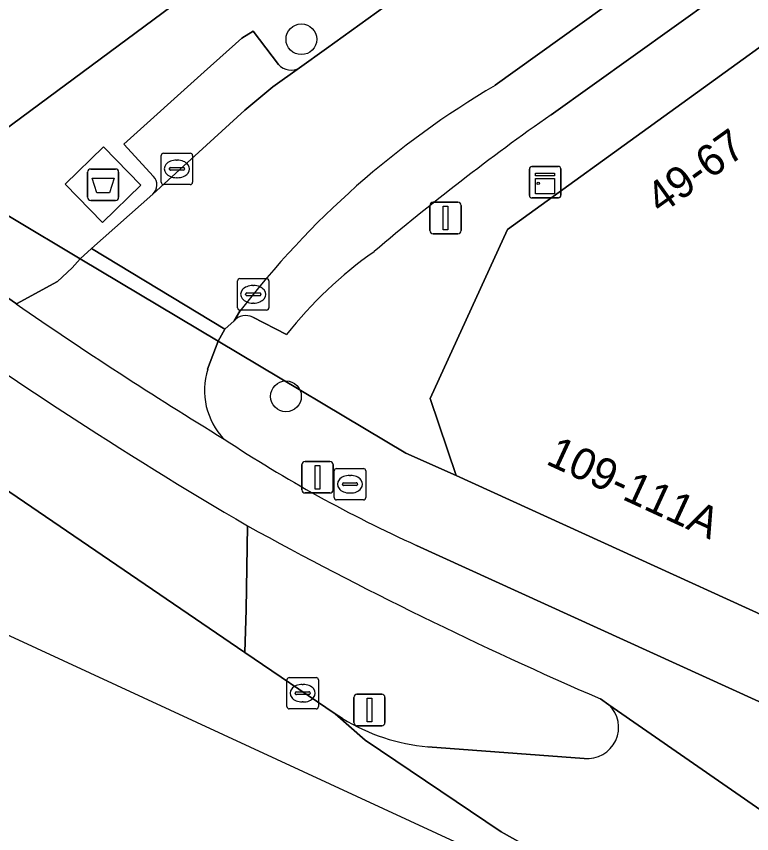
# Model space of a CAD drawing. Extents: x 161881 to 162523, y 381678 to 382381.
# Drawn here: x 162165.21 to 162188.61, y 381835.76 to 381861.78 of the extents above; entities that cross this region are included whole.
import ezdxf

# ---------------------------------------------------------------- set-up
doc = ezdxf.new("R2010")
doc.units = 0
for name, color, linetype in [('IMGEO_Afval_apart_plaats', 7, 'Continuous'), ('IMGEO_Berm_groen', 7, 'Continuous'), ('IMGEO_Boom', 7, 'Continuous'), ('IMGEO_Brandkraan', 7, 'Continuous'), ('IMGEO_Fietspad_open', 7, 'Continuous'), ('IMGEO_Kast', 7, 'Continuous'), ('IMGEO_Kolk', 7, 'Continuous'), ('IMGEO_Lichtmast', 7, 'Continuous'), ('IMGEO_Pand', 7, 'Continuous'), ('IMGEO_Pand_nummerreeks', 7, 'Continuous'), ('IMGEO_Parkeervlak_open', 7, 'Continuous'), ('IMGEO_Rijbaan_lokaal_gesloten', 7, 'Continuous'), ('IMGEO_Rijbaan_lokaal_open', 7, 'Continuous'), ('IMGEO_Voetpad_gesloten', 7, 'Continuous'), ('IMGEO_Voetpad_open', 7, 'Continuous')]:
    doc.layers.add(name, color=color, linetype=linetype)

msp = doc.modelspace()

# ---------------------------------------------------------------- linework, layer by layer
at = {"layer": 'IMGEO_Afval_apart_plaats'}
for p, q in [((162167.573, 381856.917), (162168.363, 381856.917)), ((162168.363, 381856.917), (162167.573, 381856.917)), ((162167.473, 381856.017), (162167.473, 381856.817)), ((162167.473, 381856.817), (162167.473, 381856.017)), ((162168.463, 381856.817), (162168.463, 381856.017)), ((162168.463, 381856.017), (162168.463, 381856.817)), ((162168.363, 381855.917), (162167.573, 381855.917)), ((162167.573, 381855.917), (162168.363, 381855.917))]:
    msp.add_line(p, q, dxfattribs=at)
msp.add_lwpolyline([(162167.616, 381856.631), (162168.32, 381856.631), (162168.171, 381856.161), (162167.765, 381856.161), (162167.616, 381856.631)], dxfattribs=at)
for centre, start, end in [((162167.573, 381856.817), 90, 180), ((162167.573, 381856.817), 90, 180), ((162168.363, 381856.817), 0, 90), ((162168.363, 381856.817), 360, 90), ((162167.573, 381856.017), 180, 270), ((162167.573, 381856.017), 180, 270), ((162168.363, 381856.017), 270, 0), ((162168.363, 381856.017), 270, 0)]:
    msp.add_arc(centre, 0.1, start, end, dxfattribs=at)
at = {"layer": 'IMGEO_Berm_groen'}
for points in [[(162172.562, 381845.561), (162172.524, 381842.897), (162172.48, 381841.526), (162175.355, 381839.579), (162175.591, 381839.426)], [(162184.069, 381839.866), (162183.799, 381840.053)], [(162178.306, 381838.523), (162183.281, 381838.158)]]:
    msp.add_lwpolyline(points, dxfattribs=at)
for centre, radius, start, end in [((162236.795, 381962.387), 133.32, 241.19739, 246.57753), ((162183.382, 381839.147), 0.994, 264.1725, 46.2942), ((162178.879, 381844.779), 6.282, 238.4392, 264.7669)]:
    msp.add_arc(centre, radius, start, end, dxfattribs=at)
at = {"layer": 'IMGEO_Boom'}
for centre in [(162174.279, 381861.047), (162173.788, 381849.681)]:
    msp.add_circle(centre, 0.489, dxfattribs=at)
at = {"layer": 'IMGEO_Brandkraan'}
for p, q in [((162175.326, 381846.459), (162175.326, 381847.311)), ((162175.401, 381847.385), (162176.253, 381847.385)), ((162176.327, 381847.311), (162176.327, 381846.459)), ((162175.814, 381847.165), (162175.839, 381847.165)), ((162175.585, 381846.879), (162175.585, 381846.891)), ((162176.023, 381846.842), (162175.625, 381846.842)), ((162175.628, 381846.928), (162176.026, 381846.928)), ((162176.069, 381846.891), (162176.069, 381846.879)), ((162175.837, 381846.605), (162175.812, 381846.605)), ((162176.253, 381846.385), (162175.401, 381846.385))]:
    msp.add_line(p, q, dxfattribs=at)
for points in [[(162175.326, 381846.459), (162175.326, 381847.311)], [(162175.401, 381847.385), (162176.253, 381847.385)], [(162176.327, 381847.311), (162176.327, 381846.459)], [(162176.253, 381846.385), (162175.401, 381846.385)]]:
    msp.add_lwpolyline(points, dxfattribs=at)
for centre, radius, start, end in [((162175.403, 381847.309), 0.0765, 91.552, 178.448), ((162175.403, 381847.309), 0.0765, 91.552, 178.448), ((162176.251, 381847.309), 0.0765, 1.552, 88.448), ((162176.251, 381847.309), 0.0765, 1.552, 88.448), ((162175.625, 381846.888), 0.0403, 85.8775, 175.7526), ((162175.622, 381846.878), 0.0366, 178.938, 274.7102), ((162176.026, 381846.885), 0.043, 264.8664, 352.4533), ((162176.03, 381846.89), 0.0386, 1.7309, 96.639), ((162175.403, 381846.461), 0.0765, 181.552, 268.448), ((162175.403, 381846.461), 0.0765, 181.552, 268.448), ((162176.251, 381846.461), 0.0765, 271.552, 358.448), ((162176.251, 381846.461), 0.0765, 271.552, 358.448)]:
    msp.add_arc(centre, radius, start, end, dxfattribs=at)
for centre, major_axis, ratio, start_param, end_param in [((162175.813, 381846.885), (-0.387, 0.002), 0.722429, 4.712389, 7.853982), ((162175.838, 381846.885), (-0.39, 0.002), 0.717154, 1.570796, 4.712389)]:
    msp.add_ellipse(centre, major_axis=major_axis, ratio=ratio, start_param=start_param, end_param=end_param, dxfattribs=at)
at = {"layer": 'IMGEO_Fietspad_open'}
for points in [[(162165.207, 381852.621), (162159.359, 381856.676), (162153.733, 381860.844), (162148.22, 381865.171), (162143.628, 381869.029), (162139.164, 381873.055), (162135.64, 381876.643), (162133.655, 381878.876), (162129.811, 381883.512), (162122.303, 381893.442)], [(162297.281, 381790.934), (162283.991, 381796.906), (162276.913, 381800.086), (162237.824, 381817.651), (162177.947, 381844.935)], [(162183.799, 381840.053), (162184.069, 381839.866), (162192.812, 381833.805), (162194.089, 381833.367), (162198.754, 381831.251), (162197.694, 381828.855), (162197.222, 381827.799), (162199.963, 381826.58), (162201.558, 381830.008), (162248.9, 381808.653), (162250.093, 381808.023), (162257.97, 381806.387), (162264.876, 381803.292), (162275.916, 381798.35), (162283.117, 381795.079), (162296.058, 381789.157)]]:
    msp.add_lwpolyline(points, dxfattribs=at)
for centre, radius, start, end in [((162242.708, 381965.423), 138.879, 233.95977, 239.66292), ((162245.71, 381969.21), 141.682, 235.37531, 238.56599), ((162196.27, 381885.32), 44.347, 236.5431, 245.5958), ((162236.795, 381962.387), 133.32, 241.19739, 246.57753)]:
    msp.add_arc(centre, radius, start, end, dxfattribs=at)
at = {"layer": 'IMGEO_Kast'}
for p, q in [((162181.537, 381856.073), (162181.537, 381856.914)), ((162181.537, 381856.914), (162181.537, 381856.073)), ((162181.612, 381856.998), (162182.453, 381856.998)), ((162182.453, 381856.998), (162181.612, 381856.998)), ((162182.537, 381856.923), (162182.537, 381856.082)), ((162182.537, 381856.082), (162182.537, 381856.923)), ((162182.462, 381855.998), (162181.621, 381855.998)), ((162181.621, 381855.998), (162182.462, 381855.998))]:
    msp.add_line(p, q, dxfattribs=at)
for points in [[(162181.732, 381856.788), (162182.332, 381856.788), (162182.332, 381856.703), (162181.732, 381856.703), (162181.732, 381856.788)], [(162181.732, 381856.613), (162182.332, 381856.613), (162182.332, 381856.124), (162181.732, 381856.124), (162181.732, 381856.613)]]:
    msp.add_lwpolyline(points, dxfattribs=at)
msp.add_circle((162181.816, 381856.462), 0.0377, dxfattribs=at)
for centre, start, end in [((162181.615, 381856.92), 92.4484, 184.2845), ((162181.615, 381856.92), 92.4484, 184.2845), ((162182.459, 381856.92), 2.4484, 94.2845), ((162182.459, 381856.92), 2.4484, 94.2845), ((162182.459, 381856.076), 272.4484, 4.2845), ((162182.459, 381856.076), 272.4484, 4.2845), ((162181.615, 381856.076), 182.4484, 274.2845), ((162181.615, 381856.076), 182.4484, 274.2845)]:
    msp.add_arc(centre, 0.0779, start, end, dxfattribs=at)
at = {"layer": 'IMGEO_Kolk'}
for p, q in [((162169.892, 381857.42), (162170.744, 381857.42)), ((162169.817, 381856.494), (162169.817, 381857.346)), ((162170.305, 381857.2), (162170.33, 381857.2)), ((162170.818, 381857.346), (162170.818, 381856.494)), ((162170.076, 381856.914), (162170.076, 381856.926)), ((162170.514, 381856.877), (162170.116, 381856.877)), ((162170.119, 381856.963), (162170.517, 381856.963)), ((162170.56, 381856.926), (162170.56, 381856.914)), ((162170.328, 381856.64), (162170.303, 381856.64)), ((162170.744, 381856.42), (162169.892, 381856.42)), ((162172.246, 381852.503), (162172.246, 381853.355)), ((162172.321, 381853.429), (162173.173, 381853.429)), ((162173.247, 381853.355), (162173.247, 381852.503)), ((162172.548, 381852.972), (162172.946, 381852.972)), ((162172.734, 381853.209), (162172.759, 381853.209)), ((162172.505, 381852.923), (162172.505, 381852.935)), ((162172.943, 381852.886), (162172.545, 381852.886)), ((162172.989, 381852.935), (162172.989, 381852.923)), ((162172.757, 381852.649), (162172.732, 381852.649)), ((162173.173, 381852.429), (162172.321, 381852.429)), ((162173.895, 381840.733), (162174.747, 381840.733)), ((162173.82, 381839.807), (162173.82, 381840.659)), ((162174.308, 381840.513), (162174.333, 381840.513)), ((162174.821, 381840.659), (162174.821, 381839.807)), ((162174.079, 381840.227), (162174.079, 381840.239)), ((162174.122, 381840.276), (162174.52, 381840.276)), ((162174.563, 381840.239), (162174.563, 381840.227)), ((162174.517, 381840.19), (162174.119, 381840.19)), ((162174.331, 381839.953), (162174.306, 381839.953)), ((162174.747, 381839.733), (162173.895, 381839.733))]:
    msp.add_line(p, q, dxfattribs=at)
for points in [[(162169.892, 381857.42), (162170.744, 381857.42)], [(162169.817, 381856.494), (162169.817, 381857.346)], [(162170.818, 381857.346), (162170.818, 381856.494)], [(162170.744, 381856.42), (162169.892, 381856.42)], [(162172.246, 381852.503), (162172.246, 381853.355)], [(162172.321, 381853.429), (162173.173, 381853.429)], [(162173.247, 381853.355), (162173.247, 381852.503)], [(162173.173, 381852.429), (162172.321, 381852.429)], [(162173.895, 381840.733), (162174.747, 381840.733)], [(162173.82, 381839.807), (162173.82, 381840.659)], [(162174.821, 381840.659), (162174.821, 381839.807)], [(162174.747, 381839.733), (162173.895, 381839.733)]]:
    msp.add_lwpolyline(points, dxfattribs=at)
for centre, radius, start, end in [((162169.894, 381857.344), 0.0765, 91.552, 178.448), ((162169.894, 381857.344), 0.0765, 91.552, 178.448), ((162170.742, 381857.344), 0.0765, 1.552, 88.448), ((162170.742, 381857.344), 0.0765, 1.552, 88.448), ((162170.116, 381856.923), 0.0403, 85.8775, 175.7526), ((162170.113, 381856.913), 0.0366, 178.938, 274.7102), ((162170.517, 381856.92), 0.043, 264.8664, 352.4533), ((162170.521, 381856.925), 0.0386, 1.7309, 96.639), ((162169.894, 381856.496), 0.0765, 181.552, 268.448), ((162169.894, 381856.496), 0.0765, 181.552, 268.448), ((162170.742, 381856.496), 0.0765, 271.552, 358.448), ((162170.742, 381856.496), 0.0765, 271.552, 358.448), ((162172.323, 381853.353), 0.0765, 91.552, 178.448), ((162172.323, 381853.353), 0.0765, 91.552, 178.448), ((162173.171, 381853.353), 0.0765, 1.552, 88.448), ((162173.171, 381853.353), 0.0765, 1.552, 88.448), ((162172.545, 381852.932), 0.0403, 85.8775, 175.7526), ((162172.95, 381852.934), 0.0386, 1.7309, 96.639), ((162172.542, 381852.922), 0.0366, 178.938, 274.7102), ((162172.946, 381852.929), 0.043, 264.8664, 352.4533), ((162172.323, 381852.505), 0.0765, 181.552, 268.448), ((162172.323, 381852.505), 0.0765, 181.552, 268.448), ((162173.171, 381852.505), 0.0765, 271.552, 358.448), ((162173.171, 381852.505), 0.0765, 271.552, 358.448), ((162173.897, 381840.657), 0.0765, 91.552, 178.448), ((162173.897, 381840.657), 0.0765, 91.552, 178.448), ((162174.745, 381840.657), 0.0765, 1.552, 88.448), ((162174.745, 381840.657), 0.0765, 1.552, 88.448), ((162174.119, 381840.236), 0.0403, 85.8775, 175.7526), ((162174.116, 381840.226), 0.0366, 178.938, 274.7102), ((162174.52, 381840.233), 0.043, 264.8664, 352.4533), ((162174.524, 381840.238), 0.0386, 1.7309, 96.639), ((162173.897, 381839.809), 0.0765, 181.552, 268.448), ((162173.897, 381839.809), 0.0765, 181.552, 268.448), ((162174.745, 381839.809), 0.0765, 271.552, 358.448), ((162174.745, 381839.809), 0.0765, 271.552, 358.448)]:
    msp.add_arc(centre, radius, start, end, dxfattribs=at)
for centre, major_axis, ratio, start_param, end_param in [((162170.304, 381856.92), (-0.387, 0.002), 0.722429, 4.712389, 7.853982), ((162170.329, 381856.92), (-0.39, 0.002), 0.717154, 1.570796, 4.712389), ((162172.733, 381852.929), (-0.387, 0.002), 0.722429, 4.712389, 7.853982), ((162172.758, 381852.929), (-0.39, 0.002), 0.717154, 1.570796, 4.712389), ((162174.307, 381840.233), (-0.387, 0.002), 0.722429, 4.712389, 7.853982), ((162174.332, 381840.233), (-0.39, 0.002), 0.717154, 1.570796, 4.712389)]:
    msp.add_ellipse(centre, major_axis=major_axis, ratio=ratio, start_param=start_param, end_param=end_param, dxfattribs=at)
at = {"layer": 'IMGEO_Lichtmast'}
for p, q in [((162178.472, 381855.859), (162179.262, 381855.859)), ((162179.262, 381855.859), (162178.472, 381855.859)), ((162178.372, 381854.959), (162178.372, 381855.759)), ((162178.372, 381855.759), (162178.372, 381854.959)), ((162179.362, 381855.759), (162179.362, 381854.959)), ((162179.362, 381854.959), (162179.362, 381855.759)), ((162179.262, 381854.859), (162178.472, 381854.859)), ((162178.472, 381854.859), (162179.262, 381854.859)), ((162174.297, 381846.707), (162174.297, 381847.507)), ((162174.297, 381847.507), (162174.297, 381846.707)), ((162174.397, 381847.607), (162175.187, 381847.607)), ((162175.187, 381847.607), (162174.397, 381847.607)), ((162175.287, 381847.507), (162175.287, 381846.707)), ((162175.287, 381846.707), (162175.287, 381847.507)), ((162175.187, 381846.607), (162174.397, 381846.607)), ((162174.397, 381846.607), (162175.187, 381846.607)), ((162175.948, 381839.298), (162175.948, 381840.098)), ((162175.948, 381840.098), (162175.948, 381839.298)), ((162176.048, 381840.198), (162176.838, 381840.198)), ((162176.838, 381840.198), (162176.048, 381840.198)), ((162176.938, 381840.098), (162176.938, 381839.298)), ((162176.938, 381839.298), (162176.938, 381840.098)), ((162176.838, 381839.198), (162176.048, 381839.198)), ((162176.048, 381839.198), (162176.838, 381839.198))]:
    msp.add_line(p, q, dxfattribs=at)
for points in [[(162178.792, 381855.734), (162178.942, 381855.734), (162178.942, 381854.984), (162178.792, 381854.984), (162178.792, 381855.734)], [(162174.717, 381847.482), (162174.867, 381847.482), (162174.867, 381846.732), (162174.717, 381846.732), (162174.717, 381847.482)], [(162176.368, 381840.073), (162176.518, 381840.073), (162176.518, 381839.323), (162176.368, 381839.323), (162176.368, 381840.073)]]:
    msp.add_lwpolyline(points, dxfattribs=at)
for centre, start, end in [((162178.472, 381855.759), 90, 180), ((162178.472, 381855.759), 90, 180), ((162179.262, 381855.759), 0, 90), ((162179.262, 381855.759), 360, 90), ((162178.472, 381854.959), 180, 270), ((162178.472, 381854.959), 180, 270), ((162179.262, 381854.959), 270, 0), ((162179.262, 381854.959), 270, 0), ((162174.397, 381847.507), 90, 180), ((162174.397, 381847.507), 90, 180), ((162175.187, 381847.507), 0, 90), ((162175.187, 381847.507), 360, 90), ((162174.397, 381846.707), 180, 270), ((162174.397, 381846.707), 180, 270), ((162175.187, 381846.707), 270, 0), ((162175.187, 381846.707), 270, 0), ((162176.048, 381840.098), 90, 180), ((162176.048, 381840.098), 90, 180), ((162176.838, 381840.098), 0, 90), ((162176.838, 381840.098), 360, 90), ((162176.048, 381839.298), 180, 270), ((162176.048, 381839.298), 180, 270), ((162176.838, 381839.298), 270, 0), ((162176.838, 381839.298), 270, 0)]:
    msp.add_arc(centre, 0.1, start, end, dxfattribs=at)
at = {"layer": 'IMGEO_Pand'}
for points in [[(162167.706, 381866.247), (162166.625, 381867.135), (162166.397, 381869.331), (162167.982, 381870.977), (162172.99, 381864.214), (162173.176, 381864.352), (162176.595, 381866.681), (162173.642, 381870.716), (162171.2, 381874.055), (162168.933, 381877.15), (162167.482, 381875.329), (162166.814, 381874.49), (162162.639, 381869.248), (162160.713, 381866.829), (162156.495, 381861.533), (162162.832, 381856.692), (162170.693, 381862.513), (162168.29, 381864.451), (162167.194, 381865.56)], [(162196.913, 381858.497), (162201.802, 381856.284), (162202.159, 381857.074), (162191.173, 381862.471), (162180.837, 381854.994), (162178.376, 381849.609), (162179.207, 381847.165), (162189.628, 381842.404)]]:
    msp.add_lwpolyline(points, close=True, dxfattribs=at)
at = {"layer": 'IMGEO_Parkeervlak_open'}
for points in [[(162212.528, 381882.597), (162203.872, 381876.38), (162180.448, 381859.581)], [(162182.228, 381858.647), (162187.449, 381862.392), (162186.929, 381863.221)], [(162173.553, 381860.247), (162172.749, 381861.307), (162172.384, 381861.078), (162171.188, 381860.007), (162168.627, 381857.706), (162169.576, 381856.681)], [(162169.555, 381856.117), (162172.481, 381858.791), (162173.371, 381859.537), (162174.221, 381860.14)], [(162172.323, 381852.389), (162172.135, 381852.084)], [(162172.73, 381852.199), (162173.804, 381851.649)]]:
    msp.add_lwpolyline(points, dxfattribs=at)
for centre, radius, start, end in [((162173.949, 381860.583), 0.52, 220.3046, 301.4948), ((162194.807, 381835.174), 28.317, 120.4684, 142.5601), ((162227.388, 381794.436), 78.501, 125.11899, 130.32212), ((162169.286, 381856.409), 0.397, 312.6327, 43.1026), ((162184.541, 381843.096), 13.727, 125.3918, 141.4617), ((162172.505, 381851.766), 0.488, 62.5418, 139.3364)]:
    msp.add_arc(centre, radius, start, end, dxfattribs=at)
at = {"layer": 'IMGEO_Rijbaan_lokaal_gesloten'}
for points in [[(162157.474, 381846.239), (162163.289, 381842.84), (162270.956, 381793.049), (162271.685, 381794.828), (162265.892, 381797.201), (162264.88, 381797.509), (162260.412, 381799.413), (162255.206, 381801.667), (162254.636, 381801.98), (162216.47, 381819.118), (162200.955, 381826.085), (162199.963, 381826.58), (162197.222, 381827.799), (162186.613, 381832.56), (162184.638, 381833.581), (162180.636, 381835.815), (162176.308, 381838.737), (162175.355, 381839.579), (162172.48, 381841.526), (162156.84, 381852.193), (162155.688, 381852.991), (162152.445, 381855.182), (162146.893, 381858.988)], [(162184.849, 381834.538), (162188.858, 381834.274), (162189.051, 381834.251), (162192.812, 381833.805), (162184.069, 381839.866)], [(162175.591, 381839.426), (162175.355, 381839.579), (162176.308, 381838.737), (162180.636, 381835.815), (162184.638, 381833.581), (162184.487, 381833.678)], [(162183.281, 381838.158), (162178.306, 381838.523)]]:
    msp.add_lwpolyline(points, dxfattribs=at)
for centre, radius, start, end in [((162183.382, 381839.147), 0.994, 264.1725, 46.2942), ((162178.879, 381844.779), 6.282, 238.4392, 264.7669)]:
    msp.add_arc(centre, radius, start, end, dxfattribs=at)
at = {"layer": 'IMGEO_Rijbaan_lokaal_open'}
for points in [[(162180.448, 381859.581), (162203.872, 381876.38), (162212.528, 381882.597), (162213.447, 381883.269), (162220.372, 381888.318), (162222.952, 381890.129), (162223.84, 381890.752), (162221.475, 381894.082)], [(162221.037, 381893.752), (162218.181, 381891.71), (162206.52, 381883.338), (162205.695, 381882.731), (162201.378, 381879.615), (162196.109, 381875.864), (162195.238, 381875.244), (162181.253, 381865.225), (162181.154, 381865.154), (162177.47, 381862.483), (162175.076, 381860.748), (162174.221, 381860.14), (162173.371, 381859.537), (162172.481, 381858.791), (162169.555, 381856.117), (162167.602, 381854.382), (162171.848, 381851.823), (162172.135, 381852.084), (162172.323, 381852.389)], [(162171.296, 381850.551), (162171.631, 381851.44), (162167.236, 381854.058), (162166.981, 381853.768), (162166.522, 381853.342), (162165.207, 381852.621)], [(162160.998, 381853.125), (162158.34, 381852.564), (162156.84, 381852.193), (162172.48, 381841.526), (162172.524, 381842.897), (162172.562, 381845.561)]]:
    msp.add_lwpolyline(points, dxfattribs=at)
for centre, radius, start, end in [((162194.807, 381835.174), 28.317, 120.4684, 142.5601), ((162242.708, 381965.423), 138.879, 233.95977, 239.66292), ((162245.71, 381969.21), 141.682, 235.37531, 238.56599), ((162173.434, 381849.877), 2.241, 162.5105, 223.9849)]:
    msp.add_arc(centre, radius, start, end, dxfattribs=at)
at = {"layer": 'IMGEO_Voetpad_gesloten'}
msp.add_lwpolyline([(162167.986, 381857.619), (162166.766, 381856.436), (162167.95, 381855.215), (162169.17, 381856.398)], close=True, dxfattribs=at)
at = {"layer": 'IMGEO_Voetpad_open'}
for points in [[(162222.611, 381898.266), (162222.089, 381899.341), (162219.928, 381897.942), (162200.679, 381884.262), (162189.26, 381875.839), (162187.895, 381874.832), (162187.997, 381874.692), (162184.9, 381872.437), (162184.296, 381873.278), (162182.635, 381872.084), (162180.973, 381870.888), (162181.45, 381870.226), (162178.278, 381867.945), (162176.595, 381866.681), (162173.176, 381864.352), (162172.99, 381864.214), (162170.693, 381862.513), (162162.832, 381856.692), (162167.236, 381854.058), (162167.602, 381854.382), (162169.555, 381856.117)], [(162172.135, 381852.084), (162171.848, 381851.823), (162171.631, 381851.44), (162177.609, 381847.871), (162179.207, 381847.165), (162178.376, 381849.609), (162180.837, 381854.994), (162191.173, 381862.471), (162200.189, 381868.993), (162201.278, 381868.442), (162203.258, 381871.214), (162208.741, 381875.18), (162209.012, 381875.04), (162210.218, 381876.081), (162210.308, 381875.962), (162214.928, 381879.343), (162214.81, 381879.508), (162219.757, 381883.039), (162221.85, 381884.587), (162226.702, 381888.049)], [(162148.22, 381865.171), (162153.733, 381860.844), (162159.359, 381856.676), (162165.207, 381852.621), (162166.522, 381853.342), (162166.981, 381853.768), (162167.236, 381854.058), (162162.832, 381856.692), (162156.495, 381861.533), (162156.403, 381861.418), (162152.281, 381864.662), (162148.108, 381867.983)], [(162174.221, 381860.14), (162175.076, 381860.748), (162177.47, 381862.483), (162177.177, 381862.887), (162180.861, 381865.558)], [(162186.929, 381863.221), (162187.449, 381862.392), (162182.228, 381858.647)], [(162169.576, 381856.681), (162168.627, 381857.706), (162171.188, 381860.007), (162172.384, 381861.078), (162172.749, 381861.307), (162173.553, 381860.247)], [(162173.804, 381851.649), (162172.73, 381852.199)], [(162203.692, 381835.979), (162194.508, 381840.175), (162194.384, 381840.231), (162189.628, 381842.404), (162179.207, 381847.165), (162177.609, 381847.871), (162171.631, 381851.44), (162171.296, 381850.551)], [(162177.947, 381844.935), (162237.824, 381817.651), (162276.913, 381800.086), (162283.991, 381796.906), (162297.281, 381790.934)]]:
    msp.add_lwpolyline(points, dxfattribs=at)
for points in [[(162167.95, 381855.215), (162166.766, 381856.436), (162167.986, 381857.619), (162169.17, 381856.398)], [(162167.236, 381854.058), (162171.631, 381851.44), (162171.848, 381851.823), (162167.602, 381854.382)]]:
    msp.add_lwpolyline(points, close=True, dxfattribs=at)
for centre, radius, start, end in [((162173.949, 381860.583), 0.52, 220.3046, 301.4948), ((162227.388, 381794.436), 78.501, 125.11899, 130.32212), ((162169.286, 381856.409), 0.397, 312.6327, 43.1026), ((162184.541, 381843.096), 13.727, 125.3918, 141.4617), ((162172.505, 381851.766), 0.488, 62.5418, 139.3364), ((162173.434, 381849.877), 2.241, 162.5105, 223.9849), ((162196.27, 381885.32), 44.347, 236.5431, 245.5958)]:
    msp.add_arc(centre, radius, start, end, dxfattribs=at)

# ---------------------------------------------------------------- texts
at = {"layer": 'IMGEO_Pand_nummerreeks'}
for s, rotation, p in [('49-67', 35.6838, (162185.719, 381855.45)), ('109-111A', 335.2482, (162182.024, 381847.542))]:
    msp.add_text(s, height=1, rotation=rotation, dxfattribs=at).set_placement(p)

doc.saveas('drawing.dxf')
